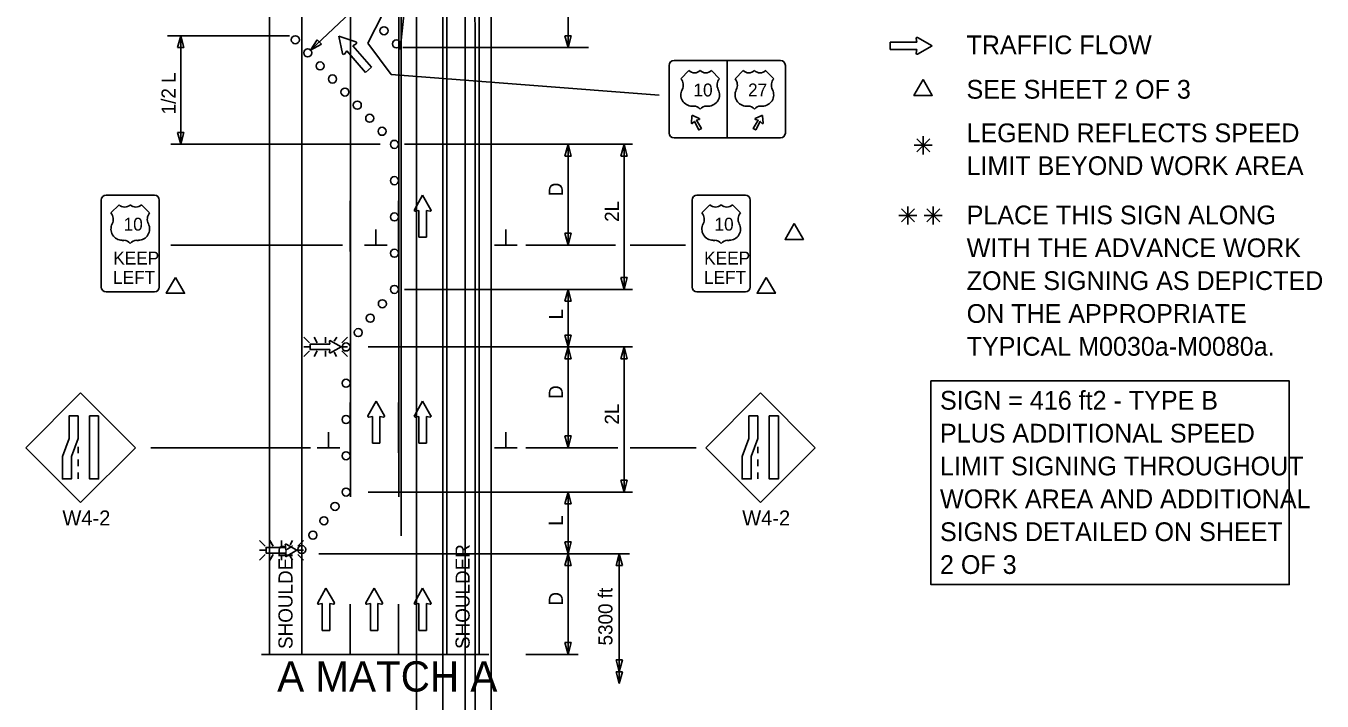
# Model space of a CAD drawing. Extents: x 16728 to 19504, y 5553 to 7079.
# Drawn here: x 16787 to 17430, y 6057 to 6392 of the extents above; entities that cross this region are included whole.
import ezdxf

# ---------------------------------------------------------------- set-up
doc = ezdxf.new("R2010")
doc.units = 0
for name, color, linetype in [('ALI_LEGAL_EX', 7, 'Continuous'), ('MT_SCRATCH_LEVEL_E', 7, 'Continuous'), ('PAVT_EDGE_EX', 7, 'Continuous'), ('TRAFFIC_SIGNS_PR', 7, 'Continuous'), ('TYPICAL_EX', 7, 'Continuous'), ('TYPICAL_TEXT_DIMEN_EX', 7, 'Continuous'), ('TYPICAL_TEXT_DIMEN_PR', 7, 'Continuous')]:
    doc.layers.add(name, color=color, linetype=linetype)

msp = doc.modelspace()

# ---------------------------------------------------------------- linework, layer by layer
at = {"layer": 'ALI_LEGAL_EX'}
for p, q in [((16980.68, 6974.12), (16980.68, 6155.98)), ((17004.68, 6974.12), (17004.68, 6155.98)), ((16980.68, 6877.04), (16980.68, 6013.12)), ((17004.68, 6877.04), (17004.68, 6013.12)), ((16973.01, 6139.03), (16973.01, 6639.38)), ((16993.65, 6024.8), (16993.65, 6525.15)), ((17017.65, 6024.8), (17017.65, 6525.15)), ((16947.82, 6158.38), (16947.82, 6435.06)), ((16971.82, 6158.38), (16971.82, 6435.06)), ((17009.75, 5773.57), (17009.75, 6383.76))]:
    msp.add_line(p, q, dxfattribs=at)
for points in [[(16972.46, 6380.33), (16975.08, 6405.19)], [(16947.69, 6280.11), (16947.69, 6305.11)], [(16971.69, 6280.11), (16971.69, 6305.11)], [(16947.69, 6180.11), (16947.69, 6205.11)], [(16971.69, 6180.11), (16971.69, 6205.11)], [(16947.69, 6080.11), (16947.69, 6105.11)], [(16971.69, 6080.11), (16971.69, 6105.11)]]:
    msp.add_lwpolyline(points, dxfattribs=at)
msp.add_arc((16645.75, 6383.76), 364, 0, 40.19088, dxfattribs=at)
at = {"layer": 'MT_SCRATCH_LEVEL_E'}
for p, q in [((17228.51, 6385.75), (17228.82, 6383.97)), ((17236.43, 6382.12), (17229.19, 6386.23)), ((17228.82, 6383.97), (17215.57, 6383.97)), ((17215.57, 6383.97), (17215.57, 6380.23)), ((17215.57, 6380.23), (17228.82, 6380.23)), ((17228.82, 6380.23), (17228.51, 6378.45)), ((17229.19, 6377.97), (17236.43, 6382.12)), ((16983.67, 6307.98), (16979.56, 6300.74)), ((16987.81, 6300.74), (16983.67, 6307.98)), ((16980.04, 6300.06), (16981.82, 6300.37)), ((16981.82, 6300.37), (16981.82, 6287.11)), ((16985.56, 6287.11), (16985.56, 6300.37)), ((16985.56, 6300.37), (16987.33, 6300.06)), ((16981.82, 6287.11), (16985.56, 6287.11)), ((16960.6, 6205.82), (16956.49, 6198.58)), ((16964.74, 6198.58), (16960.6, 6205.82)), ((16983.67, 6205.82), (16979.56, 6198.58)), ((16987.81, 6198.58), (16983.67, 6205.82)), ((16956.97, 6197.9), (16958.74, 6198.21)), ((16958.74, 6198.21), (16958.74, 6184.96)), ((16962.49, 6184.96), (16962.49, 6198.21)), ((16962.49, 6198.21), (16964.26, 6197.9)), ((16980.04, 6197.9), (16981.82, 6198.21)), ((16981.82, 6198.21), (16981.82, 6184.96)), ((16985.56, 6184.96), (16985.56, 6198.21)), ((16985.56, 6198.21), (16987.33, 6197.9)), ((16958.74, 6184.96), (16962.49, 6184.96)), ((16981.82, 6184.96), (16985.56, 6184.96)), ((16935.71, 6112.92), (16931.6, 6105.68)), ((16939.86, 6105.68), (16935.71, 6112.92)), ((16959.61, 6112.92), (16955.5, 6105.68)), ((16963.76, 6105.68), (16959.61, 6112.92)), ((16983.67, 6112.92), (16979.56, 6105.68)), ((16987.81, 6105.68), (16983.67, 6112.92)), ((16932.08, 6105), (16933.86, 6105.31)), ((16933.86, 6105.31), (16933.86, 6092.06)), ((16937.6, 6092.06), (16937.6, 6105.31)), ((16937.6, 6105.31), (16939.38, 6105)), ((16955.99, 6105), (16957.76, 6105.31)), ((16957.76, 6105.31), (16957.76, 6092.06)), ((16961.5, 6092.06), (16961.5, 6105.31)), ((16961.5, 6105.31), (16963.28, 6105)), ((16980.04, 6105), (16981.82, 6105.31)), ((16981.82, 6105.31), (16981.82, 6092.06)), ((16985.56, 6092.06), (16985.56, 6105.31)), ((16985.56, 6105.31), (16987.33, 6105)), ((16933.86, 6092.06), (16937.6, 6092.06)), ((16957.76, 6092.06), (16961.5, 6092.06)), ((16981.82, 6092.06), (16985.56, 6092.06))]:
    msp.add_line(p, q, dxfattribs=at)
for centre, start, end in [((17228.97, 6385.82), 60.42484, 189.96381), ((17228.97, 6378.38), 170.03619, 299.77312), ((16979.96, 6300.52), 150.42484, 279.96381), ((16987.41, 6300.52), 260.03619, 29.77312), ((16956.89, 6198.36), 150.42484, 279.96381), ((16964.33, 6198.36), 260.03619, 29.77312), ((16979.96, 6198.36), 150.42484, 279.96381), ((16987.41, 6198.36), 260.03619, 29.77312), ((16932.01, 6105.46), 150.42484, 279.96381), ((16939.45, 6105.46), 260.03619, 29.77312), ((16955.91, 6105.46), 150.42484, 279.96381), ((16963.35, 6105.46), 260.03619, 29.77312), ((16979.96, 6105.46), 150.42484, 279.96381), ((16987.41, 6105.46), 260.03619, 29.77312)]:
    msp.add_arc(centre, 0.463, start, end, dxfattribs=at)
at = {"layer": 'PAVT_EDGE_EX'}
for p, q in [((16907.69, 6435.06), (16907.69, 6080.11)), ((16923.69, 6435.06), (16923.69, 6080.11)), ((16995.69, 6435.06), (16995.69, 6080.11)), ((17011.69, 6435.06), (17011.69, 6080.11))]:
    msp.add_line(p, q, dxfattribs=at)
msp.add_arc((17311.7, 6356.79), 300, 180, 180.00000277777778, dxfattribs=at)
at = {"layer": 'TRAFFIC_SIGNS_PR'}
for p, q in [((17105.99, 6372.38), (17105.99, 6338.78)), ((17108.39, 6374.78), (17161.19, 6374.78)), ((17134.79, 6374.78), (17134.79, 6336.38)), ((17163.59, 6372.38), (17163.59, 6338.78)), ((17116.96, 6343.73), (17117.25, 6347.35)), ((17117.62, 6347.57), (17120.9, 6346)), ((17151.95, 6347.57), (17148.67, 6346)), ((17152.61, 6343.73), (17152.32, 6347.35)), ((17108.39, 6336.38), (17161.19, 6336.38)), ((16850.64, 6307.99), (16826.64, 6307.99)), ((17143.76, 6307.99), (17119.76, 6307.99)), ((16824.24, 6305.59), (16824.24, 6262.39)), ((16853.04, 6262.39), (16853.04, 6305.59)), ((17117.36, 6305.59), (17117.36, 6262.39)), ((17146.16, 6262.39), (17146.16, 6305.59)), ((16826.64, 6259.99), (16850.64, 6259.99)), ((17119.76, 6259.99), (17143.76, 6259.99)), ((16927.47, 6234.78), (16924.65, 6237.6)), ((16929.77, 6237.6), (16931.39, 6234.78)), ((16935.55, 6234.78), (16935.55, 6237.6)), ((16941.02, 6237.6), (16939.82, 6235.51)), ((16946.46, 6237.6), (16943.64, 6234.78)), ((16927.47, 6232.75), (16924.65, 6232.75)), ((16927.47, 6230.72), (16924.65, 6227.89)), ((16931.42, 6230.72), (16929.79, 6227.9)), ((16935.55, 6230.72), (16935.55, 6227.9)), ((16943.64, 6232.75), (16946.46, 6232.75)), ((16946.46, 6227.9), (16943.64, 6230.72)), ((16939.74, 6230.08), (16941, 6227.9)), ((16814.01, 6209.85), (16786.86, 6182.69)), ((16841.17, 6182.69), (16814.01, 6209.85)), ((17151.25, 6209.85), (17124.1, 6182.69)), ((17178.41, 6182.69), (17151.25, 6209.85)), ((16786.86, 6182.69), (16814.01, 6155.54)), ((16812.77, 6183.18), (16812.77, 6179.98)), ((16814.01, 6155.54), (16841.17, 6182.69)), ((17124.1, 6182.69), (17151.25, 6155.54)), ((17150.01, 6183.18), (17150.01, 6179.98)), ((17151.25, 6155.54), (17178.41, 6182.69)), ((16812.77, 6176.78), (16812.77, 6173.58)), ((17150.01, 6176.78), (17150.01, 6173.58)), ((16812.77, 6170.38), (16812.77, 6167.18)), ((17150.01, 6170.38), (17150.01, 6167.18)), ((16905.6, 6133.83), (16902.78, 6136.65)), ((16907.89, 6136.65), (16909.52, 6133.83)), ((16913.68, 6133.83), (16913.68, 6136.65)), ((16919.15, 6136.65), (16917.94, 6134.55)), ((16924.59, 6136.65), (16921.77, 6133.83)), ((16905.6, 6131.8), (16902.78, 6131.8)), ((16905.6, 6129.76), (16902.78, 6126.94)), ((16909.55, 6129.76), (16907.92, 6126.94)), ((16913.68, 6129.76), (16913.68, 6126.94)), ((16917.86, 6129.13), (16919.13, 6126.94)), ((16921.77, 6131.8), (16924.59, 6131.8)), ((16924.59, 6126.95), (16921.77, 6129.76))]:
    msp.add_line(p, q, dxfattribs=at)
for points in [[(17120.86, 6345.52), (17119.45, 6345.13), (17121.96, 6341.15), (17120.63, 6340.38), (17118.45, 6344.55), (17117.41, 6343.53)], [(17148.71, 6345.52), (17150.12, 6345.13), (17147.61, 6341.15), (17148.94, 6340.38), (17151.13, 6344.55), (17152.17, 6343.53)], [(16937.38, 6235.43), (16937.61, 6234.13), (16927.89, 6234.13), (16927.89, 6231.39), (16937.61, 6231.39), (16937.38, 6230.09)], [(16937.88, 6229.73), (16943.19, 6232.75), (16937.88, 6235.79)], [(16915.51, 6134.48), (16915.74, 6133.18), (16906.02, 6133.18), (16906.02, 6130.44), (16915.74, 6130.44), (16915.51, 6129.13)], [(16916.01, 6128.78), (16921.32, 6131.8), (16916.01, 6134.84)]]:
    msp.add_lwpolyline(points, dxfattribs=at)
for points in [[(16812.77, 6198.43), (16812.77, 6187.25), (16809.42, 6178.37), (16809.42, 6167.18), (16804.93, 6167.18), (16804.93, 6178.37), (16808.27, 6187.25), (16808.27, 6198.43)], [(16822.9, 6198.43), (16822.9, 6167.18), (16818.41, 6167.18), (16818.41, 6198.43)], [(17150.01, 6198.43), (17150.01, 6187.25), (17146.66, 6178.37), (17146.66, 6167.18), (17142.17, 6167.18), (17142.17, 6178.37), (17145.51, 6187.25), (17145.51, 6198.43)], [(17160.14, 6198.43), (17160.14, 6167.18), (17155.65, 6167.18), (17155.65, 6198.43)]]:
    msp.add_lwpolyline(points, close=True, dxfattribs=at)
for centre in [(16964.5, 6389.58), (16920.51, 6385.09), (16970.7, 6383.05), (16926.66, 6378.6), (16932.8, 6372.11), (16938.95, 6365.62), (16945.1, 6359.14), (16951.25, 6352.65), (16957.4, 6346.16), (16963.55, 6339.68), (16969.69, 6333.19), (16969.69, 6333.19), (16969.69, 6315.19), (16969.69, 6297.19), (16969.69, 6279.19), (16969.69, 6261.24), (16963.69, 6254.1), (16957.69, 6246.96), (16951.69, 6239.82), (16945.69, 6232.68), (16945.69, 6214.68), (16945.69, 6196.68), (16945.69, 6178.68), (16945.69, 6160.68), (16940.2, 6153.54), (16934.7, 6146.42), (16929.2, 6139.29), (16923.71, 6132.17)]:
    msp.add_circle(centre, 2, dxfattribs=at)
for centre, radius, start, end in [((17108.39, 6372.38), 2.4, 90, 180), ((17108.39, 6372.38), 2.4, 90, 180), ((17161.19, 6372.38), 2.4, 0, 90), ((17117.51, 6347.33), 0.26, 64.48226, 175.51774), ((17152.06, 6347.33), 0.26, 4.48226, 115.51774), ((17117.22, 6343.71), 0.26, 175.51775, 314.01151), ((17120.79, 6345.77), 0.26, 285.9885, 64.48226), ((17148.79, 6345.77), 0.26, 115.51774, 254.0115), ((17152.35, 6343.71), 0.26, 225.98849, 4.48225), ((17108.39, 6338.78), 2.4, 180, 270), ((17161.19, 6338.78), 2.4, 270, 0), ((16826.64, 6305.59), 2.4, 90, 180), ((16850.64, 6305.59), 2.4, 0, 90), ((17119.76, 6305.59), 2.4, 90, 180), ((17143.76, 6305.59), 2.4, 0, 90), ((16826.64, 6262.39), 2.4, 180, 270), ((16850.64, 6262.39), 2.4, 270, 0), ((17119.76, 6262.39), 2.4, 180, 270), ((17143.76, 6262.39), 2.4, 270, 0), ((16937.72, 6235.49), 0.341, 61.48329, 189.95933), ((16937.72, 6230.03), 0.341, 170.73078, 298.89165), ((16915.85, 6134.54), 0.341, 61.48329, 189.95933), ((16915.84, 6129.08), 0.341, 170.73078, 298.89165)]:
    msp.add_arc(centre, radius, start, end, dxfattribs=at)
at = {"layer": 'TYPICAL_EX'}
for p, q in [((17111.74, 6365.78), (17115.74, 6369.78)), ((17130.94, 6365.78), (17126.94, 6369.78)), ((17138.63, 6365.78), (17142.63, 6369.78)), ((17157.84, 6365.78), (17153.83, 6369.78)), ((17117.33, 6352.17), (17118.13, 6352.17)), ((17125.34, 6352.17), (17124.54, 6352.17)), ((17144.23, 6352.17), (17145.03, 6352.17)), ((17152.24, 6352.17), (17151.44, 6352.17)), ((16829.04, 6299.19), (16833.04, 6303.19)), ((16848.24, 6299.19), (16844.24, 6303.19)), ((17122.16, 6299.19), (17126.16, 6303.19)), ((17141.36, 6299.19), (17137.36, 6303.19)), ((16834.63, 6285.58), (16835.43, 6285.58)), ((16842.64, 6285.58), (16841.84, 6285.58)), ((17127.76, 6285.58), (17128.56, 6285.58)), ((17135.77, 6285.58), (17134.97, 6285.58))]:
    msp.add_line(p, q, dxfattribs=at)
for centre, radius, start, end in [((17107.95, 6362.58), 4.96, 333.09768, 40.19361), ((17118.54, 6372.7), 4.04, 226.14041, 313.85958), ((17124.14, 6372.7), 4.04, 226.14042, 313.85959), ((17134.73, 6362.58), 4.96, 139.80639, 206.90233), ((17134.84, 6362.58), 4.96, 333.09768, 40.19361), ((17145.44, 6372.7), 4.04, 226.14041, 313.85958), ((17151.04, 6372.7), 4.04, 226.14042, 313.85959), ((17161.63, 6362.58), 4.96, 139.80639, 206.90233), ((17117.34, 6357.77), 5.59, 152.6698, 269.90132), ((17125.33, 6357.77), 5.59, 270.09868, 27.3302), ((17144.24, 6357.77), 5.59, 152.6698, 269.90132), ((17152.23, 6357.77), 5.59, 270.09868, 27.3302), ((17118.14, 6348.17), 4.01, 37.1038, 90.13853), ((17124.53, 6348.17), 4.01, 89.86147, 142.8962), ((17145.04, 6348.17), 4.01, 37.1038, 90.13853), ((17151.43, 6348.17), 4.01, 89.86147, 142.8962), ((16835.84, 6306.11), 4.04, 226.14041, 313.85958), ((16841.44, 6306.11), 4.04, 226.14042, 313.85959), ((17128.96, 6306.11), 4.04, 226.14041, 313.85958), ((17134.56, 6306.11), 4.04, 226.14042, 313.85959), ((16825.24, 6295.99), 4.96, 333.09768, 40.19361), ((16852.03, 6295.99), 4.96, 139.80639, 206.90233), ((17118.37, 6295.99), 4.96, 333.09768, 40.19361), ((17145.15, 6295.99), 4.96, 139.80639, 206.90233), ((16834.64, 6291.18), 5.59, 152.6698, 269.90132), ((16842.63, 6291.18), 5.59, 270.09868, 27.3302), ((17127.77, 6291.18), 5.59, 152.6698, 269.90132), ((17135.76, 6291.18), 5.59, 270.09868, 27.3302), ((16835.44, 6281.58), 4.01, 37.1038, 90.13853), ((16841.83, 6281.58), 4.01, 89.86147, 142.8962), ((17128.57, 6281.58), 4.01, 37.1038, 90.13853), ((17134.96, 6281.58), 4.01, 89.86147, 142.8962)]:
    msp.add_arc(centre, radius, start, end, dxfattribs=at)
at = {"layer": 'TYPICAL_TEXT_DIMEN_EX'}
msp.add_lwpolyline([(17235.82, 6215.87), (17413.54, 6215.87), (17413.54, 6114.78), (17235.82, 6114.78)], close=True, dxfattribs=at)
at = {"layer": 'TYPICAL_TEXT_DIMEN_PR'}
for p, q in [((17055.79, 6411.86), (17055.79, 6381.25)), ((16950.66, 6401.27), (16928.11, 6379.97)), ((16963.92, 6397.9), (16956.54, 6383.4)), ((16857.02, 6387.09), (16917.6, 6387.09)), ((16862.12, 6381.22), (16863.69, 6387.09)), ((16863.69, 6387.09), (16863.69, 6333.24)), ((16863.69, 6387.09), (16865.26, 6381.22)), ((16928.11, 6379.97), (16931.29, 6385.14)), ((16931.29, 6385.14), (16932.37, 6384)), ((16950.58, 6384.04), (16942.16, 6386.94)), ((16942.16, 6386.94), (16943.96, 6378.24)), ((17055.79, 6381.25), (17054.22, 6387.11)), ((17054.22, 6387.11), (17055.79, 6387.11)), ((17055.79, 6387.11), (17057.36, 6387.11)), ((17057.36, 6387.11), (17055.79, 6381.25)), ((16863.69, 6381.22), (16862.12, 6381.22)), ((16865.26, 6381.22), (16863.69, 6381.22)), ((16933.45, 6382.85), (16928.11, 6379.97)), ((16932.37, 6384), (16933.45, 6382.85)), ((16944.82, 6378.03), (16946.03, 6379.53)), ((16946.03, 6379.53), (16955.35, 6368.9)), ((16949.03, 6382.16), (16950.68, 6383.16)), ((16958.35, 6371.53), (16949.03, 6382.16)), ((16956.54, 6383.4), (16968.11, 6367.89)), ((16973.81, 6381.25), (17065.97, 6381.25)), ((16955.35, 6368.9), (16958.35, 6371.53)), ((16968.11, 6367.89), (17101.05, 6357.66)), ((16863.69, 6333.24), (16862.12, 6339.1)), ((16862.12, 6339.1), (16863.69, 6339.1)), ((16863.69, 6339.1), (16865.26, 6339.1)), ((16865.26, 6339.1), (16863.69, 6333.24)), ((17228.83, 6335.93), (17235.2, 6329.55)), ((17235.2, 6335.93), (17228.83, 6329.55)), ((17232.02, 6332.74), (17232.02, 6337.19)), ((16962.58, 6333.24), (16858.69, 6333.24)), ((17087.84, 6333.24), (16974.74, 6333.24)), ((17054.22, 6327.38), (17055.79, 6333.24)), ((17055.79, 6327.38), (17054.22, 6327.38)), ((17055.79, 6333.24), (17057.36, 6327.38)), ((17055.79, 6333.24), (17055.79, 6283.24)), ((17057.36, 6327.38), (17055.79, 6327.38)), ((17082.03, 6327.38), (17083.6, 6333.24)), ((17083.6, 6327.38), (17082.03, 6327.38)), ((17083.6, 6333.24), (17083.6, 6261.24)), ((17083.6, 6333.24), (17085.17, 6327.38)), ((17085.17, 6327.38), (17083.6, 6327.38)), ((17232.02, 6332.74), (17227.48, 6332.74)), ((17232.02, 6332.74), (17235.2, 6332.74)), ((17232.02, 6332.74), (17236.49, 6332.74)), ((17232.02, 6332.74), (17232.02, 6328.24)), ((17224.42, 6297.95), (17224.42, 6302.41)), ((17236.98, 6297.95), (17236.98, 6302.41)), ((17224.42, 6297.95), (17219.89, 6297.95)), ((17227.61, 6301.14), (17221.23, 6294.76)), ((17221.24, 6301.14), (17227.61, 6294.76)), ((17224.42, 6297.95), (17227.61, 6297.95)), ((17224.42, 6297.95), (17228.9, 6297.95)), ((17224.42, 6297.95), (17224.42, 6293.45)), ((17236.98, 6297.95), (17232.44, 6297.95)), ((17233.79, 6301.14), (17240.16, 6294.76)), ((17240.16, 6301.14), (17233.79, 6294.76)), ((17236.98, 6297.95), (17240.16, 6297.95)), ((17236.98, 6297.95), (17241.45, 6297.95)), ((17236.98, 6297.95), (17236.98, 6293.45)), ((16960.44, 6283.24), (16960.44, 6291.02)), ((17024.92, 6283.24), (17024.92, 6291.02)), ((17055.79, 6283.24), (17054.22, 6289.1)), ((17054.22, 6289.1), (17055.79, 6289.1)), ((17055.79, 6289.1), (17057.36, 6289.1)), ((17057.36, 6289.1), (17055.79, 6283.24)), ((16858.79, 6283.24), (16943.91, 6283.24)), ((16966.07, 6283.24), (16954.82, 6283.24)), ((17030.54, 6283.24), (17019.29, 6283.24)), ((17079.37, 6283.24), (17034.79, 6283.24)), ((17114.03, 6283.24), (17086.59, 6283.24)), ((17083.6, 6261.24), (17082.03, 6267.1)), ((17082.03, 6267.1), (17083.6, 6267.1)), ((17083.6, 6267.1), (17085.17, 6267.1)), ((17085.17, 6267.1), (17083.6, 6261.24)), ((16974.74, 6261.24), (17087.84, 6261.24)), ((17054.22, 6255.38), (17055.79, 6261.24)), ((17055.79, 6232.68), (17055.79, 6261.24)), ((17055.79, 6261.24), (17057.36, 6255.38)), ((17055.79, 6255.38), (17054.22, 6255.38)), ((17057.36, 6255.38), (17055.79, 6255.38)), ((17055.79, 6232.68), (17054.22, 6238.54)), ((17054.22, 6238.54), (17055.79, 6238.54)), ((17055.79, 6238.54), (17057.36, 6238.54)), ((17057.36, 6238.54), (17055.79, 6232.68)), ((17087.84, 6232.68), (16956.69, 6232.68)), ((17054.22, 6226.81), (17055.79, 6232.68)), ((17055.79, 6232.68), (17055.79, 6182.68)), ((17055.79, 6232.68), (17057.36, 6226.81)), ((17082.03, 6226.81), (17083.6, 6232.68)), ((17083.6, 6232.68), (17085.17, 6226.81)), ((17083.6, 6232.68), (17083.6, 6160.68)), ((17055.79, 6226.81), (17054.22, 6226.81)), ((17057.36, 6226.81), (17055.79, 6226.81)), ((17083.6, 6226.81), (17082.03, 6226.81)), ((17085.17, 6226.81), (17083.6, 6226.81)), ((16936.98, 6182.68), (16936.98, 6190.46)), ((17024.92, 6182.68), (17024.92, 6190.46)), ((17055.79, 6182.68), (17054.22, 6188.54)), ((17054.22, 6188.54), (17055.79, 6188.54)), ((17055.79, 6188.54), (17057.36, 6188.54)), ((17057.36, 6188.54), (17055.79, 6182.68)), ((16848.79, 6182.68), (16927.99, 6182.68)), ((16942.6, 6182.68), (16931.35, 6182.68)), ((17030.54, 6182.68), (17019.29, 6182.68)), ((17080.53, 6182.68), (17034.79, 6182.68)), ((17119.41, 6182.68), (17086.59, 6182.68)), ((17083.6, 6160.68), (17082.03, 6166.54)), ((17082.03, 6166.54), (17083.6, 6166.54)), ((17083.6, 6166.54), (17085.17, 6166.54)), ((17085.17, 6166.54), (17083.6, 6160.68)), ((16956.69, 6160.68), (17087.84, 6160.68)), ((17054.22, 6154.81), (17055.79, 6160.68)), ((17055.79, 6130.11), (17055.79, 6160.68)), ((17055.79, 6160.68), (17057.36, 6154.81)), ((17055.79, 6154.81), (17054.22, 6154.81)), ((17057.36, 6154.81), (17055.79, 6154.81)), ((17055.79, 6130.11), (17054.22, 6135.97)), ((17054.22, 6135.97), (17055.79, 6135.97)), ((17055.79, 6135.97), (17057.36, 6135.97)), ((17057.36, 6135.97), (17055.79, 6130.11)), ((16932.19, 6130.11), (17086.23, 6130.11)), ((16932.95, 6130.11), (17060.79, 6130.11)), ((17054.22, 6124.25), (17055.79, 6130.11)), ((17055.79, 6130.11), (17055.79, 6080.11)), ((17055.79, 6130.11), (17057.36, 6124.25)), ((17079.66, 6124.25), (17081.23, 6130.11)), ((17081.23, 6130.11), (17081.23, 6065.7)), ((17081.23, 6130.11), (17082.8, 6124.25)), ((17055.79, 6124.25), (17054.22, 6124.25)), ((17057.36, 6124.25), (17055.79, 6124.25)), ((17081.23, 6124.25), (17079.66, 6124.25)), ((17082.8, 6124.25), (17081.23, 6124.25)), ((17055.79, 6080.11), (17054.22, 6085.97)), ((17054.22, 6085.97), (17055.79, 6085.97)), ((17055.79, 6085.97), (17057.36, 6085.97)), ((17057.36, 6085.97), (17055.79, 6080.11)), ((16903.77, 6080.11), (17016.42, 6080.11)), ((17060.79, 6080.11), (17034.79, 6080.11)), ((17081.2, 6071.55), (17079.63, 6077.42)), ((17079.63, 6077.42), (17081.2, 6077.42)), ((17081.2, 6077.42), (17082.77, 6077.42)), ((17082.77, 6077.42), (17081.2, 6071.55)), ((17081.23, 6065.7), (17079.66, 6071.56)), ((17079.66, 6071.56), (17081.23, 6071.56)), ((17081.23, 6071.56), (17082.8, 6071.56)), ((17082.8, 6071.56), (17081.23, 6065.7))]:
    msp.add_line(p, q, dxfattribs=at)
for points in [[(17231.93, 6365.33), (17227.41, 6357.5), (17236.46, 6357.5)], [(17168, 6293.86), (17163.48, 6286.03), (17172.53, 6286.03)], [(16861, 6267.17), (16856.48, 6259.33), (16865.53, 6259.33)], [(17154.13, 6267.17), (17149.61, 6259.33), (17158.66, 6259.33)]]:
    msp.add_lwpolyline(points, close=True, dxfattribs=at)
for centre, start, end in [((16950.41, 6383.58), 301.27371, 71.01063), ((16944.44, 6378.34), 191.66235, 321.20132)]:
    msp.add_arc(centre, 0.494, start, end, dxfattribs=at)

# ---------------------------------------------------------------- texts
at = {"layer": 'TRAFFIC_SIGNS_PR'}
for s, height, p in [('10', 6.4, (17118, 6356.98)), ('27', 6.4, (17145.07, 6356.98)), ('10', 6.4, (16835.3, 6290.39)), ('10', 6.4, (17128.42, 6290.39)), ('KEEP', 6.4, (16830.17, 6273.59)), ('KEEP', 6.4, (17123.3, 6273.59)), ('LEFT', 6.4, (16830.08, 6263.99)), ('LEFT', 6.4, (17123.21, 6263.99)), ('W4-2', 7.44, (16804.97, 6144.1)), ('W4-2', 7.44, (17142.21, 6144.1))]:
    msp.add_text(s, height=height, dxfattribs=at).set_placement(p)
at = {"layer": 'TYPICAL_TEXT_DIMEN_EX'}
for s, p in [('TRAFFIC FLOW', (17253.47, 6377.92)), ('SEE SHEET 2 OF 3', (17253.47, 6355.87)), ('LEGEND REFLECTS SPEED', (17253.47, 6334.27)), ('LIMIT BEYOND WORK AREA', (17253.47, 6317.97)), ('PLACE THIS SIGN ALONG', (17253.56, 6293.53)), ('WITH THE ADVANCE WORK', (17253.56, 6277.23)), ('ZONE SIGNING AS DEPICTED', (17253.56, 6260.93)), ('ON THE APPROPRIATE', (17253.56, 6244.63)), ('TYPICAL M0030a-M0080a.', (17253.56, 6228.33)), ('SIGN = 416 ft2 - TYPE B', (17240.32, 6201.56)), ('PLUS ADDITIONAL SPEED', (17240.32, 6185.26)), ('LIMIT SIGNING THROUGHOUT', (17240.32, 6168.96)), ('WORK AREA AND ADDITIONAL', (17240.32, 6152.66)), ('SIGNS DETAILED ON SHEET', (17240.32, 6136.36)), ('2 OF 3', (17240.32, 6120.06))]:
    msp.add_text(s, height=9.3, dxfattribs=at).set_placement(p)
at = {"layer": 'TYPICAL_TEXT_DIMEN_PR'}
for s, p in [('1/2 L', (16861.13, 6348.1)), ('D', (17053.23, 6307.46)), ('2L', (17081.04, 6294.74)), ('L', (17053.32, 6246.32)), ('D', (17053.23, 6206.9)), ('2L', (17081.04, 6194.18)), ('L', (17053.23, 6143.97)), ('SHOULDER', (16919.13, 6082.82)), ('SHOULDER', (17006.99, 6082.82)), ('D', (17053.23, 6104.33)), ('5300 ft', (17077.82, 6084.57))]:
    msp.add_text(s, height=7, rotation=90, dxfattribs=at).set_placement(p)
msp.add_text('A MATCH A', height=15, dxfattribs=at).set_placement((16911.51, 6061.71))

doc.saveas('drawing.dxf')
